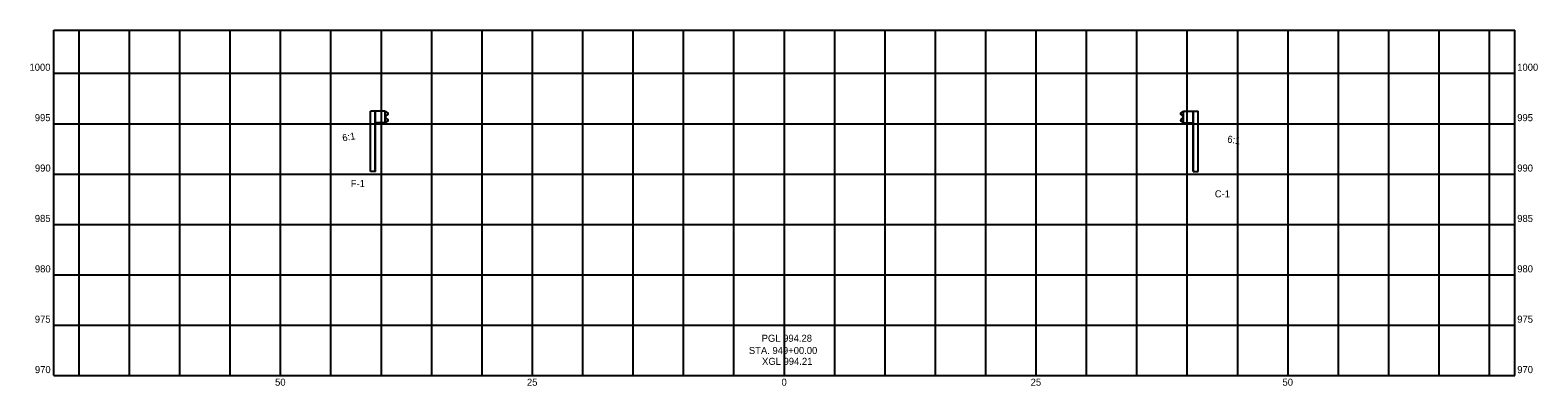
# Model space of a CAD drawing. Extents: x -75 to 75, y 969 to 1004.
import ezdxf

# ---------------------------------------------------------------- set-up
doc = ezdxf.new("R2010")
doc.units = 0
for name, color, linetype in [('RD_P_Cells', 7, 'Continuous'), ('SH_Major_Grid_Line', 7, 'Continuous'), ('SH_Text', 7, 'Continuous')]:
    doc.layers.add(name, color=color, linetype=linetype)

msp = doc.modelspace()

# ---------------------------------------------------------------- linework, layer by layer
at = {"layer": 'RD_P_Cells'}
for p, q in [((-40.61, 996.25), (-41.09, 996.25)), ((-41.09, 990.25), (-41.09, 996.25)), ((-41.07, 990.25), (-41.07, 996.25)), ((-39.61, 996.25), (-40.61, 996.25)), ((-40.61, 995.09), (-40.61, 996.25)), ((-40.61, 995.09), (-40.61, 996.25)), ((-40.59, 995.09), (-40.59, 996.25)), ((-39.61, 995.09), (-39.61, 996.25)), ((-39.6, 996.18), (-39.6, 996.18)), ((-39.6, 996.18), (-39.51, 996.17)), ((-39.6, 996.17), (-39.6, 996.18)), ((-39.6, 996.17), (-39.6, 996.17)), ((-39.52, 996.16), (-39.6, 996.17)), ((-39.6, 995.72), (-39.6, 995.72)), ((-39.6, 995.62), (-39.6, 995.72)), ((-39.6, 995.64), (-39.6, 995.7)), ((-39.6, 995.62), (-39.6, 995.62)), ((-39.59, 995.72), (-39.59, 995.72)), ((-39.59, 995.72), (-39.59, 995.62)), ((-39.59, 995.64), (-39.59, 995.7)), ((-39.59, 995.62), (-39.59, 995.62)), ((-39.56, 995.79), (-39.38, 995.93)), ((-39.37, 995.92), (-39.56, 995.78)), ((-39.56, 995.79), (-39.56, 995.79)), ((-39.56, 995.78), (-39.56, 995.78)), ((-39.56, 995.56), (-39.56, 995.56)), ((-39.56, 995.56), (-39.37, 995.42)), ((-39.56, 995.55), (-39.56, 995.55)), ((-39.37, 995.42), (-39.56, 995.55)), ((-39.52, 996.16), (-39.52, 996.16)), ((-39.37, 996.05), (-39.52, 996.16)), ((-39.51, 996.17), (-39.51, 996.17)), ((-39.51, 996.17), (-39.37, 996.06)), ((-39.51, 995.18), (-39.37, 995.29)), ((-39.37, 995.28), (-39.51, 995.17)), ((-39.5, 995.84), (-39.5, 995.84)), ((-39.49, 996.15), (-39.49, 996.15)), ((-39.49, 996.14), (-39.49, 996.14)), ((-39.49, 995.83), (-39.49, 995.83)), ((-39.38, 995.93), (-39.38, 995.93)), ((-39.37, 996.06), (-39.37, 996.06)), ((-39.37, 996.05), (-39.37, 996.05)), ((-39.37, 995.92), (-39.37, 995.92)), ((-39.37, 995.42), (-39.37, 995.42)), ((-39.37, 995.42), (-39.37, 995.42)), ((-39.37, 995.29), (-39.37, 995.29)), ((-39.37, 995.28), (-39.37, 995.28)), ((-39.34, 995.99), (-39.34, 995.99)), ((-39.34, 995.35), (-39.34, 995.35)), ((-39.33, 995.99), (-39.33, 995.99)), ((-39.33, 995.35), (-39.33, 995.35)), ((39.33, 995.99), (39.33, 995.99)), ((39.33, 995.35), (39.33, 995.35)), ((39.34, 995.99), (39.34, 995.99)), ((39.34, 995.35), (39.34, 995.35)), ((39.51, 996.17), (39.37, 996.06)), ((39.37, 996.05), (39.52, 996.16)), ((39.37, 996.06), (39.37, 996.06)), ((39.37, 996.05), (39.37, 996.05)), ((39.37, 995.92), (39.37, 995.92)), ((39.37, 995.92), (39.56, 995.78)), ((39.56, 995.56), (39.37, 995.42)), ((39.37, 995.42), (39.56, 995.55)), ((39.37, 995.42), (39.37, 995.42)), ((39.37, 995.42), (39.37, 995.42)), ((39.37, 995.29), (39.37, 995.29)), ((39.51, 995.18), (39.37, 995.29)), ((39.37, 995.28), (39.37, 995.28)), ((39.37, 995.28), (39.51, 995.17)), ((39.38, 995.93), (39.38, 995.93)), ((39.56, 995.79), (39.38, 995.93)), ((39.49, 996.15), (39.49, 996.15)), ((39.49, 996.14), (39.49, 996.14)), ((39.49, 995.83), (39.49, 995.83)), ((39.5, 995.84), (39.5, 995.84)), ((39.6, 996.18), (39.51, 996.17)), ((39.51, 996.17), (39.51, 996.17)), ((39.52, 996.16), (39.6, 996.17)), ((39.52, 996.16), (39.52, 996.16)), ((39.56, 995.79), (39.56, 995.79)), ((39.56, 995.78), (39.56, 995.78)), ((39.56, 995.56), (39.56, 995.56)), ((39.56, 995.55), (39.56, 995.55)), ((39.59, 995.72), (39.59, 995.72)), ((39.59, 995.72), (39.59, 995.62)), ((39.59, 995.64), (39.59, 995.7)), ((39.59, 995.62), (39.59, 995.62)), ((39.6, 996.18), (39.6, 996.18)), ((39.6, 996.17), (39.6, 996.18)), ((39.6, 996.17), (39.6, 996.17)), ((39.6, 995.72), (39.6, 995.72)), ((39.6, 995.62), (39.6, 995.72)), ((39.6, 995.64), (39.6, 995.7)), ((39.6, 995.62), (39.6, 995.62)), ((39.61, 996.25), (40.61, 996.25)), ((39.61, 995.09), (39.61, 996.25)), ((40.59, 995.09), (40.59, 996.25)), ((40.61, 996.25), (41.09, 996.25)), ((40.61, 995.09), (40.61, 996.25)), ((40.61, 995.09), (40.61, 996.25)), ((41.07, 990.25), (41.07, 996.25)), ((41.09, 990.25), (41.09, 996.25)), ((-39.61, 995.09), (-40.61, 995.09)), ((-40.61, 990.25), (-40.61, 995.09)), ((-40.59, 990.25), (-40.59, 995.09)), ((-39.6, 995.17), (-39.51, 995.18)), ((-39.6, 995.17), (-39.6, 995.17)), ((-39.6, 995.16), (-39.6, 995.17)), ((-39.51, 995.17), (-39.6, 995.16)), ((-39.6, 995.16), (-39.6, 995.16)), ((39.6, 995.17), (39.51, 995.18)), ((39.51, 995.17), (39.6, 995.16)), ((39.6, 995.17), (39.6, 995.17)), ((39.6, 995.16), (39.6, 995.17)), ((39.6, 995.16), (39.6, 995.16)), ((39.61, 995.09), (40.61, 995.09)), ((40.59, 990.25), (40.59, 995.09)), ((40.61, 990.25), (40.61, 995.09)), ((-40.59, 990.25), (-41.09, 990.25)), ((40.59, 990.25), (41.09, 990.25))]:
    msp.add_line(p, q, dxfattribs=at)
for points in [[(-39.58, 995.73), (-39.58, 995.61), (-39.59, 995.61), (-39.59, 995.73)], [(-39.58, 995.7), (-39.58, 995.64), (-39.56, 995.64), (-39.56, 995.7)], [(39.58, 995.7), (39.58, 995.64), (39.56, 995.64), (39.56, 995.7)], [(39.58, 995.73), (39.58, 995.61), (39.59, 995.61), (39.59, 995.73)]]:
    msp.add_lwpolyline(points, close=True, dxfattribs=at)
for centre, radius, start, end in [((-39.51, 995.72), 0.0886, 126.318, 180.0944), ((-39.51, 995.62), 0.0886, 180.0944, 233.8707), ((-39.51, 995.72), 0.0788, 126.318, 180.0944), ((-39.51, 995.62), 0.0788, 180.0944, 233.8707), ((-39.42, 995.99), 0.0787, 306.318, 53.2212), ((-39.42, 995.99), 0.0886, 306.318, 53.2212), ((-39.42, 995.35), 0.0787, 306.9675, 53.8707), ((-39.42, 995.35), 0.0886, 306.9675, 53.8707), ((39.42, 995.99), 0.0886, 126.7788, 233.682), ((39.42, 995.35), 0.0886, 126.1293, 233.0325), ((39.42, 995.99), 0.0787, 126.7788, 233.682), ((39.42, 995.35), 0.0787, 126.1293, 233.0325), ((39.51, 995.72), 0.0886, 359.9056, 53.682), ((39.51, 995.72), 0.0788, 359.9056, 53.682), ((39.51, 995.62), 0.0886, 306.1293, 359.9056), ((39.51, 995.62), 0.0788, 306.1293, 359.9056)]:
    msp.add_arc(centre, radius, start, end, dxfattribs=at)
at = {"layer": 'SH_Major_Grid_Line'}
for p, q in [((-72.5, 1004.28), (72.5, 1004.28)), ((-72.5, 970), (-72.5, 1004.28)), ((-70, 970), (-70, 1004.28)), ((-65, 970), (-65, 1004.28)), ((-60, 970), (-60, 1004.28)), ((-55, 970), (-55, 1004.28)), ((-50, 970), (-50, 1004.28)), ((-45, 970), (-45, 1004.28)), ((-40, 970), (-40, 1004.28)), ((-35, 970), (-35, 1004.28)), ((-30, 970), (-30, 1004.28)), ((-25, 970), (-25, 1004.28)), ((-20, 970), (-20, 1004.28)), ((-15, 970), (-15, 1004.28)), ((-10, 970), (-10, 1004.28)), ((-5, 970), (-5, 1004.28)), ((0, 970), (0, 1004.28)), ((5, 970), (5, 1004.28)), ((10, 970), (10, 1004.28)), ((15, 970), (15, 1004.28)), ((20, 970), (20, 1004.28)), ((25, 970), (25, 1004.28)), ((30, 970), (30, 1004.28)), ((35, 970), (35, 1004.28)), ((40, 970), (40, 1004.28)), ((45, 970), (45, 1004.28)), ((50, 970), (50, 1004.28)), ((55, 970), (55, 1004.28)), ((60, 970), (60, 1004.28)), ((65, 970), (65, 1004.28)), ((70, 970), (70, 1004.28)), ((72.5, 970), (72.5, 1004.28)), ((-72.5, 1000), (72.5, 1000)), ((-72.5, 995), (72.5, 995)), ((-72.5, 990), (72.5, 990)), ((-72.5, 985), (72.5, 985)), ((-72.5, 980), (72.5, 980)), ((-72.5, 975), (72.5, 975)), ((-72.5, 970), (72.5, 970))]:
    msp.add_line(p, q, dxfattribs=at)

# ---------------------------------------------------------------- texts
at = {"layer": 'SH_Text'}
for s, p in [('1000', (-74.93, 1000.25)), ('1000', (72.75, 1000.25)), ('995', (-74.4, 995.25)), ('995', (72.75, 995.25)), ('990', (-74.39, 990.25)), ('990', (72.75, 990.25)), ('F-1', (-43.04, 988.71)), ('C-1', (42.73, 987.69)), ('985', (-74.4, 985.25)), ('985', (72.75, 985.25)), ('980', (-74.39, 980.25)), ('980', (72.75, 980.25)), ('975', (-74.4, 975.25)), ('975', (72.75, 975.25)), ('STA. 949+00.00', (-3.52, 972.15)), ('PGL 994.28', (-2.25, 973.36)), ('XGL 994.21', (-2.21, 971.07)), ('970', (-74.39, 970.25)), ('970', (72.75, 970.25)), ('50', (-50.55, 969)), ('25', (-25.55, 969)), ('0', (-0.28, 969)), ('25', (24.45, 969)), ('50', (49.45, 969))]:
    msp.add_text(s, height=0.7, dxfattribs=at).set_placement(p)
for rotation, p in [(9.4605, (-43.82, 993.24)), (350.5395, (43.93, 993.15))]:
    msp.add_text('6:1', height=0.7, rotation=rotation, dxfattribs=at).set_placement(p)

doc.saveas('drawing.dxf')
